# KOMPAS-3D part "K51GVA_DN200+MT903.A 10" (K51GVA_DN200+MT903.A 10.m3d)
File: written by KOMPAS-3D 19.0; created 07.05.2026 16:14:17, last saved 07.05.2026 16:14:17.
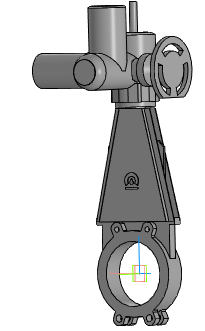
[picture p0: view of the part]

Document properties: Автор: Энергия; Полное имя файла: ..\K51GVA_DN50-DN1000+MT903.A\K51GVA_DN200+MT903.A 10.a3d

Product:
- Part/product: K51GVA_DN200+MT903.A 10
    Масса: 104.28

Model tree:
1. Операция без истории:1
